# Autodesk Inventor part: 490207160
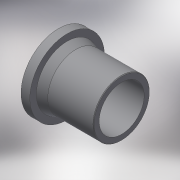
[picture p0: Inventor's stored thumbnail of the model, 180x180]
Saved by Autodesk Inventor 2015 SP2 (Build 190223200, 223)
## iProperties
Created: 2017-07
Part Number: 490207160
Material: Generic
Description: Stub Flange 160
Document SubType Name: Modeling
Designer: Кирилл
Mass: 1723.09 g
Surface Area: 2132.82 cm^2
Volume: 1723.09 cm^3
Density: 1 g/cm^3
Appearance: Default
Author: Кирилл
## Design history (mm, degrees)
derived "490207.ipt"
feature "Solid1::490207.ipt"
tag "TaggingFeature1"
body "Solid1"
other parameters: "d1" = 175, "d3" = 128, "d4" = 212, "d5" = 25, "d17" = 3.2, "d18" = 3.2, "d19" = 3.2, "d21" = 3.2, "d24" = 3.2, "d25" = 3.2, "d26" = 1.6, "d27" = 0, "d32" = 1.6, "D_" = 212, "D_1" = 175, "a_" = 25
